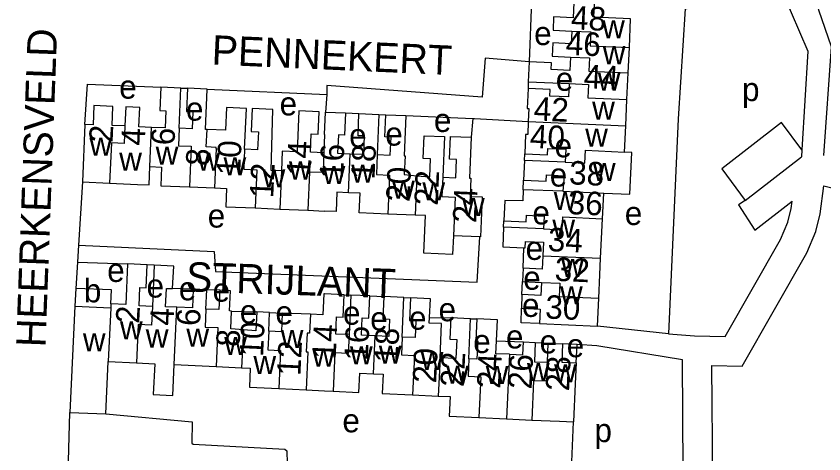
# Model space of a CAD drawing. Extents: x 163026 to 166241, y 382475 to 384501.
# Drawn here: x 164447.5 to 164584.9, y 383667.5 to 383742 of the extents above; entities that cross this region are included whole.
import ezdxf

# ---------------------------------------------------------------- set-up
doc = ezdxf.new("R2010")
doc.units = 0
for name, color, linetype in [('BLT_Basislijn', 7, 'Continuous'), ('BLT_Bebouwing', 7, 'Continuous'), ('BLT_Centroide', 7, 'Continuous'), ('BLT_Huisnummer', 7, 'Continuous'), ('BLT_Huisnummer_ tussenligend', 7, 'Continuous'), ('BLT_Onderverdeling_panden', 7, 'Continuous'), ('BLT_Straatnaam', 7, 'Continuous')]:
    doc.layers.add(name, color=color, linetype=linetype)

msp = doc.modelspace()

# ---------------------------------------------------------------- linework, layer by layer
at = {"layer": 'BLT_Basislijn'}
for p, q in [((164535.21, 383744.65), (164534.79, 383734.18)), ((164475.55, 383729.74), (164476.67, 383729.69)), ((164534.63, 383730.81), (164534.61, 383729.68)), ((164480.03, 383729.52), (164500.38, 383728.66)), ((164500.38, 383728.66), (164500.16, 383725.65)), ((164503.56, 383725.5), (164505.84, 383725.38)), ((164509.24, 383725.25), (164510.39, 383725.18)), ((164513.81, 383725.04), (164525.23, 383724.55)), ((164525.23, 383724.55), (164524.94, 383721.35)), ((164581.21, 383719.23), (164581.14, 383718.04)), ((164534.01, 383717.42), (164534.04, 383718.52)), ((164571.54, 383710.61), (164581.14, 383718.04)), ((164458.78, 383713.75), (164458.11, 383702.99)), ((164533.79, 383712.41), (164533.86, 383714.05)), ((164540.54, 383712.17), (164533.79, 383712.41)), ((164530.45, 383706.08), (164530.5, 383707.16)), ((164458.11, 383702.99), (164457.93, 383700.11)), ((164533.77, 383699.08), (164533.87, 383702.57)), ((164457.93, 383700.11), (164457.65, 383695.65)), ((164457.93, 383700.11), (164466.47, 383699.83)), ((164471.02, 383699.6), (164469.81, 383699.67)), ((164533.57, 383694.58), (164533.67, 383696.8)), ((164477.65, 383695.49), (164474.14, 383695.6)), ((164482.15, 383695.32), (164479.96, 383695.38)), ((164503.3, 383694.56), (164504.46, 383694.51)), ((164507.67, 383694.36), (164510.06, 383694.24)), ((164513.49, 383694.1), (164514.59, 383694.05)), ((164484.17, 383691.79), (164488.46, 383691.66)), ((164490.62, 383691.56), (164492.8, 383691.45)), ((164517.85, 383690.69), (164521.45, 383690.64)), ((164524.82, 383690.49), (164525.91, 383690.44)), ((164558.49, 383687.93), (164546.42, 383689.23)), ((164529.25, 383686.71), (164533.84, 383686.53)), ((164535.84, 383686.42), (164538.04, 383686.33)), ((164542.99, 383686.07), (164540.49, 383686.22)), ((164542.79, 383682.98), (164542.99, 383686.07)), ((164561.01, 383664.59), (164560.89, 383683.49))]:
    msp.add_line(p, q, dxfattribs=at)
for points in [[(164584.94, 383718.24), (164586.21, 383736.75), (164584.06, 383743.01), (164583.2, 383746.85), (164590.25, 383746.86)], [(164561.35, 383743.23), (164577.98, 383745.92), (164582.22, 383736), (164581.21, 383719.23)], [(164561.35, 383743.23), (164560.12, 383724.5), (164558.49, 383687.93)], [(164534.79, 383734.18), (164527.29, 383734.8), (164526.79, 383728.2), (164500.37, 383730.18), (164500.38, 383728.66)], [(164459.2, 383723.55), (164459.66, 383730.38), (164472.11, 383729.88)], [(164525.23, 383724.55), (164525.51, 383724.54), (164534.65, 383724.04)], [(164581.21, 383719.23), (164577.74, 383723.87), (164567.6, 383716), (164571.54, 383710.61)], [(164584.92, 383713.1), (164603, 383708.67), (164611.04, 383683.41), (164605.18, 383660.67), (164604, 383657.93), (164602.56, 383656.05), (164599.82, 383654.68), (164592.55, 383651.8), (164575.01, 383655.48), (164566.02, 383663.02), (164565.9, 383682.51)], [(164565.9, 383682.51), (164571.04, 383682.38), (164582.02, 383701.72), (164583.58, 383705.35), (164584.29, 383708.32), (164584.92, 383713.1)], [(164558.49, 383687.93), (164562.94, 383687.59), (164568.17, 383687.46), (164577.53, 383703.95), (164578.82, 383706.93), (164579.36, 383709.23), (164579.53, 383710.47)], [(164571.54, 383710.61), (164570.39, 383709.87), (164573.19, 383705.57), (164579.53, 383710.47)], [(164458.11, 383702.99), (164481.18, 383701.92), (164481.43, 383698.51), (164525.97, 383696.68), (164526.38, 383704.4)], [(164536.57, 383689.68), (164533.41, 383689.78), (164533.47, 383692.26)], [(164560.89, 383683.49), (164546.32, 383685.88), (164542.99, 383686.07)], [(164462.39, 383659.57), (164456.22, 383660.08), (164456.33, 383662.17), (164456.66, 383674.55)], [(164462.75, 383674.27), (164477.46, 383672.96), (164477.4, 383669.3), (164477.64, 383669.11), (164493.2, 383668.31), (164493.58, 383668.02), (164493.65, 383665.84), (164494.01, 383665.39), (164538.67, 383663.4)], [(164538.67, 383663.4), (164541.96, 383663.43), (164542.34, 383672.92)]]:
    msp.add_lwpolyline(points, dxfattribs=at)
at = {"layer": 'BLT_Bebouwing'}
for p, q in [((164551.64, 383732.3), (164551.84, 383736.62)), ((164534.79, 383734.18), (164534.63, 383730.81)), ((164551.43, 383727.77), (164551.64, 383732.3)), ((164475.55, 383729.74), (164472.11, 383729.88)), ((164480.03, 383729.52), (164476.67, 383729.69)), ((164551.22, 383723.28), (164551.43, 383727.77)), ((164500, 383721.83), (164500.16, 383725.65)), ((164500.16, 383725.65), (164503.56, 383725.5)), ((164505.84, 383725.38), (164509.24, 383725.25)), ((164510.39, 383725.18), (164513.81, 383725.04)), ((164459.2, 383723.55), (164458.78, 383713.75)), ((164551.02, 383718.85), (164551.22, 383723.28)), ((164534.01, 383717.42), (164533.86, 383714.05)), ((164458.78, 383713.75), (164463.42, 383713.55)), ((164477, 383712.91), (164481.27, 383712.73)), ((164533.79, 383712.41), (164533.71, 383710.53)), ((164547.3, 383707.49), (164547.5, 383711.85)), ((164488.17, 383709.33), (164492.37, 383709.14)), ((164492.37, 383709.14), (164497.15, 383708.94)), ((164497.15, 383708.94), (164500, 383708.81)), ((164515.38, 383708.11), (164510.74, 383708.3)), ((164546.95, 383700.76), (164547.3, 383707.49)), ((164526.38, 383704.4), (164521.9, 383704.59)), ((164469.81, 383699.67), (164466.47, 383699.83)), ((164533.77, 383699.08), (164533.67, 383696.8)), ((164457.65, 383695.65), (164457.51, 383692.64)), ((164479.96, 383695.38), (164477.65, 383695.49)), ((164503.3, 383694.56), (164500, 383694.71)), ((164507.67, 383694.36), (164504.46, 383694.51)), ((164513.49, 383694.1), (164510.06, 383694.24)), ((164533.57, 383694.58), (164533.47, 383692.26)), ((164546.42, 383689.23), (164546.64, 383693.97)), ((164457.51, 383692.64), (164456.66, 383674.55)), ((164490.62, 383691.56), (164488.46, 383691.66)), ((164497.59, 383691.23), (164492.8, 383691.45)), ((164517.81, 383689.71), (164517.85, 383690.69)), ((164521.45, 383690.64), (164521.29, 383687.01)), ((164524.82, 383690.49), (164521.45, 383690.64)), ((164536.57, 383689.68), (164546.42, 383689.23)), ((164533.84, 383686.53), (164535.84, 383686.42)), ((164538.04, 383686.33), (164540.49, 383686.22)), ((164462.75, 383674.27), (164463.17, 383683.18)), ((164463.17, 383683.18), (164467.97, 383682.95)), ((164481.54, 383682.35), (164485.87, 383682.14)), ((164492.2, 383678.58), (164496.83, 383678.36)), ((164496.83, 383678.36), (164500, 383678.21)), ((164500, 383678.21), (164501.47, 383678.15)), ((164514.97, 383677.51), (164519.33, 383677.31)), ((164456.66, 383674.55), (164462.75, 383674.27)), ((164526.26, 383673.65), (164530.95, 383673.44)), ((164530.95, 383673.44), (164535.27, 383673.24))]:
    msp.add_line(p, q, dxfattribs=at)
for points in [[(164542.38, 383744.28), (164542.26, 383741.71), (164538.96, 383741.86), (164538.86, 383739.59), (164542.07, 383739.44)], [(164551.84, 383736.62), (164552.06, 383741.49), (164545.82, 383741.78), (164545.93, 383744.12)], [(164542.07, 383739.44), (164541.97, 383737.27), (164538.82, 383737.42), (164538.72, 383735.16), (164541.85, 383735.01)], [(164541.85, 383735.01), (164541.74, 383732.75), (164538.56, 383732.9), (164538.61, 383734.01), (164534.79, 383734.18)], [(164472.11, 383729.88), (164471.94, 383725.89), (164472.97, 383725.85), (164472.85, 383722.95), (164470.57, 383723.05)], [(164475.26, 383722.9), (164475.55, 383729.74)], [(164476.67, 383729.69), (164476.51, 383725.72), (164477.56, 383725.67), (164477.44, 383722.8), (164475.26, 383722.9)], [(164534.61, 383729.68), (164534.45, 383726.27), (164534.75, 383726.26), (164534.65, 383724.04)], [(164541.61, 383730.49), (164541.51, 383728.23), (164538.34, 383728.37), (164538.39, 383729.5), (164534.61, 383729.68)], [(164534.63, 383730.81), (164541.61, 383730.49)], [(164479.99, 383722.69), (164479.75, 383722.7), (164480.03, 383729.52)], [(164466.02, 383723.28), (164463.84, 383723.37), (164463.98, 383726.6), (164460.75, 383726.74), (164460.61, 383723.49), (164459.2, 383723.55)], [(164470.57, 383723.05), (164468.39, 383723.14), (164468.53, 383726.44), (164466.15, 383726.54), (164466.02, 383723.28)], [(164486.39, 383719.31), (164486.68, 383726.27), (164483.31, 383726.41), (164483.14, 383722.56), (164479.99, 383722.69)], [(164492.65, 383715.65), (164490.89, 383715.73), (164491.2, 383726.08), (164487.65, 383726.23), (164487.49, 383722.35), (164488.72, 383722.3), (164488.59, 383719.21), (164486.39, 383719.31)], [(164499.87, 383718.72), (164497.58, 383718.82), (164497.71, 383721.93), (164498.89, 383721.88), (164499.05, 383725.69), (164495.62, 383725.84), (164495.33, 383718.88), (164492.79, 383718.98), (164492.65, 383715.65)], [(164503.56, 383725.5), (164503.4, 383721.71), (164502.33, 383721.76), (164502.2, 383718.66), (164504.33, 383718.57)], [(164504.33, 383718.57), (164506.65, 383718.47), (164506.78, 383721.59), (164505.68, 383721.63), (164505.84, 383725.38)], [(164509.24, 383725.25), (164508.96, 383718.42)], [(164508.96, 383718.42), (164511.17, 383718.33), (164511.3, 383721.37), (164510.24, 383721.42), (164510.39, 383725.18)], [(164513.81, 383725.04), (164513.53, 383718.21), (164513.68, 383718.2), (164513.55, 383715.01), (164515.66, 383714.82)], [(164534.65, 383724.04), (164534.55, 383721.83), (164534.19, 383721.84), (164534.04, 383718.52)], [(164500, 383721.83), (164499.87, 383718.72)], [(164515.66, 383714.82), (164517.87, 383714.64), (164518, 383717.71), (164516.78, 383717.76), (164516.94, 383721.61), (164520.37, 383721.47), (164520.08, 383714.58)], [(164520.08, 383714.58), (164522.32, 383714.48), (164522.45, 383717.59), (164521.26, 383717.64), (164521.43, 383721.49), (164524.94, 383721.35)], [(164524.94, 383721.35), (164524.65, 383714.42), (164524.9, 383714.41), (164524.77, 383711.29), (164526.82, 383711.2), (164526.54, 383704.39), (164526.38, 383704.4)], [(164534.04, 383718.52), (164537.9, 383718.35), (164537.96, 383719.47), (164541.03, 383719.33), (164540.93, 383717.1)], [(164547.5, 383711.85), (164551.94, 383711.67), (164552.27, 383718.79), (164551.02, 383718.85)], [(164540.93, 383717.1), (164534.01, 383717.42)], [(164463.42, 383713.55), (164468.16, 383713.34), (164470.14, 383713.26), (164470.28, 383716.37)], [(164470.28, 383716.37), (164472.27, 383716.29), (164472.13, 383713.12), (164477, 383712.91)], [(164533.86, 383714.05), (164537.69, 383713.87), (164537.74, 383714.95), (164540.73, 383714.81), (164540.54, 383712.17)], [(164481.27, 383712.73), (164483.33, 383712.64), (164483.2, 383709.54), (164488.17, 383709.33)], [(164504.05, 383711.92), (164502.08, 383712.01), (164501.94, 383708.73), (164500, 383708.81)], [(164510.74, 383708.3), (164505.88, 383708.51), (164506.02, 383711.84), (164504.05, 383711.92)], [(164533.71, 383710.53), (164530.66, 383710.62), (164530.5, 383707.16)], [(164521.9, 383704.59), (164521.77, 383701.43), (164516.9, 383701.63), (164517.17, 383708.04), (164515.38, 383708.11)], [(164530.5, 383707.16), (164534.27, 383706.98), (164534.32, 383708.09), (164537.36, 383707.95), (164537.26, 383705.76)], [(164530.45, 383706.08), (164530.29, 383702.74), (164533.87, 383702.57)], [(164537.26, 383705.76), (164530.45, 383706.08)], [(164533.87, 383702.57), (164534.13, 383702.56), (164534.18, 383703.63), (164537.21, 383703.49), (164537.1, 383701.21)], [(164537.1, 383701.21), (164537, 383698.93), (164533.77, 383699.08)], [(164546.64, 383693.97), (164546.82, 383697.93), (164546.95, 383700.76)], [(164466.47, 383699.83), (164466.15, 383692.88), (164463.63, 383693)], [(164470.69, 383692.57), (164468.42, 383692.67), (164468.56, 383695.8), (164469.63, 383695.75), (164469.81, 383699.67)], [(164471.02, 383699.6), (164470.69, 383692.57)], [(164474.14, 383695.6), (164474.32, 383699.45), (164471.02, 383699.6)], [(164536.88, 383696.66), (164536.78, 383694.44), (164533.57, 383694.58)], [(164533.67, 383696.8), (164536.88, 383696.66)], [(164463.63, 383693), (164463.74, 383695.37), (164457.65, 383695.65)], [(164474.86, 383692.43), (164472.94, 383692.53), (164473.09, 383695.65), (164474.14, 383695.6)], [(164477.65, 383695.49), (164477.5, 383692.31), (164474.86, 383692.43)], [(164479.81, 383692.13), (164479.96, 383695.38)], [(164482.15, 383695.32), (164482, 383692.03), (164479.81, 383692.13)], [(164484.17, 383691.79), (164483.84, 383691.8), (164484, 383695.23), (164482.15, 383695.32)], [(164500, 383694.71), (164499.86, 383694.71), (164499.69, 383691.17), (164497.59, 383691.23)], [(164504.16, 383687.77), (164501.89, 383687.87), (164502.03, 383690.81), (164503.13, 383690.76), (164503.3, 383694.56)], [(164504.46, 383694.51), (164504.16, 383687.77)], [(164508.6, 383687.55), (164506.27, 383687.66), (164506.4, 383690.62), (164507.5, 383690.57), (164507.67, 383694.36)], [(164510.06, 383694.24), (164509.91, 383690.45), (164511.06, 383690.4), (164510.93, 383687.45), (164508.6, 383687.55)], [(164513.21, 383687.36), (164513.49, 383694.1)], [(164514.59, 383694.05), (164514.42, 383690.19), (164515.54, 383690.14), (164515.41, 383687.26), (164513.21, 383687.36)], [(164517.85, 383690.69), (164517.99, 383693.89), (164514.59, 383694.05)], [(164486.17, 383688.58), (164484.03, 383688.74), (164484.17, 383691.79)], [(164488.46, 383691.66), (164488.3, 383688.42), (164486.17, 383688.58)], [(164490.48, 383688.36), (164490.62, 383691.56)], [(164492.8, 383691.45), (164492.65, 383688.24), (164490.48, 383688.36)], [(164533.47, 383692.26), (164536.68, 383692.11), (164536.57, 383689.68)], [(164524.52, 383683.64), (164524.82, 383690.49)], [(164525.91, 383690.44), (164525.75, 383686.75), (164526.04, 383686.73), (164525.9, 383683.58), (164524.52, 383683.64)], [(164529.25, 383686.71), (164529.41, 383690.29), (164525.91, 383690.44)], [(164519.63, 383683.82), (164519.89, 383689.67), (164517.81, 383689.71)], [(164521.29, 383687.01), (164522.48, 383686.95), (164522.33, 383683.7), (164519.63, 383683.82)], [(164531.45, 383684.43), (164529.15, 383684.53), (164529.25, 383686.71)], [(164531.45, 383684.43), (164533.74, 383684.32), (164533.84, 383686.53)], [(164535.84, 383686.42), (164535.7, 383683.12), (164537.89, 383683.08)], [(164537.89, 383683.08), (164538.04, 383686.33)], [(164540.49, 383686.22), (164540.35, 383683.09), (164542.79, 383682.98)], [(164467.97, 383682.95), (164471.1, 383682.8), (164470.85, 383677.6), (164474.15, 383677.44), (164474.4, 383682.68)], [(164542.79, 383682.98), (164542.63, 383679.41), (164542.34, 383672.92)], [(164474.4, 383682.68), (164481.54, 383682.35)], [(164485.87, 383682.14), (164487.34, 383682.07), (164487.19, 383678.81), (164492.2, 383678.58)], [(164501.47, 383678.15), (164505.84, 383677.94), (164505.99, 383681.2), (164508.31, 383681.09)], [(164508.31, 383681.09), (164509.94, 383681.02), (164509.8, 383677.74), (164514.97, 383677.51)], [(164519.33, 383677.31), (164521.33, 383677.22), (164521.18, 383673.88), (164526.26, 383673.65)], [(164535.27, 383673.24), (164539.96, 383673.03), (164542.34, 383672.92)]]:
    msp.add_lwpolyline(points, dxfattribs=at)
at = {"layer": 'BLT_Onderverdeling_panden'}
for p, q in [((164470.28, 383716.37), (164470.57, 383723.05)), ((164534.65, 383724.04), (164551.22, 383723.28)), ((164481.56, 383719.45), (164481.27, 383712.73)), ((164504.05, 383711.92), (164504.33, 383718.57)), ((164492.65, 383715.65), (164492.37, 383709.14)), ((164515.66, 383714.82), (164515.38, 383708.11)), ((164540.54, 383712.17), (164547.5, 383711.85)), ((164537.1, 383701.21), (164546.95, 383700.76)), ((164457.51, 383692.64), (164463.6, 383692.35)), ((164463.63, 383693), (164463.6, 383692.35)), ((164463.6, 383692.35), (164463.17, 383683.18)), ((164474.4, 383682.68), (164474.86, 383692.43)), ((164486.17, 383688.58), (164485.87, 383682.14)), ((164508.31, 383681.09), (164508.6, 383687.55)), ((164531.45, 383684.43), (164530.95, 383673.44)), ((164519.63, 383683.82), (164519.33, 383677.31))]:
    msp.add_line(p, q, dxfattribs=at)
for points in [[(164542.07, 383739.44), (164545.28, 383739.29), (164545.17, 383736.92), (164551.84, 383736.62)], [(164541.85, 383735.01), (164545.08, 383734.86), (164544.97, 383732.6), (164551.64, 383732.3)], [(164541.61, 383730.49), (164544.87, 383730.34), (164544.76, 383728.08), (164551.43, 383727.77)], [(164466.02, 383723.28), (164465.89, 383720.32), (164463.71, 383720.41), (164463.42, 383713.55)], [(164475.26, 383722.9), (164475.13, 383719.91), (164477.31, 383719.82), (164477, 383712.91)], [(164481.56, 383719.45), (164481.57, 383719.63), (164479.86, 383719.71), (164479.99, 383722.69)], [(164486.39, 383719.31), (164486.24, 383715.92), (164488.45, 383715.83), (164488.17, 383709.33)], [(164499.87, 383718.72), (164499.73, 383715.35), (164497.44, 383715.44), (164497.15, 383708.94)], [(164540.93, 383717.1), (164544.25, 383716.94), (164544.36, 383719.17), (164551.02, 383718.85)], [(164508.96, 383718.42), (164508.83, 383715), (164511.02, 383714.91), (164510.74, 383708.3)], [(164520.08, 383714.58), (164519.93, 383711.26), (164522.18, 383711.16), (164521.9, 383704.59)], [(164537.26, 383705.76), (164540.41, 383705.61), (164540.51, 383707.8), (164547.3, 383707.49)], [(164536.88, 383696.66), (164540, 383696.51), (164539.9, 383694.29), (164546.64, 383693.97)], [(164470.69, 383692.57), (164470.54, 383689.38), (164468.27, 383689.49), (164467.97, 383682.95)], [(164479.81, 383692.13), (164479.66, 383689.06), (164481.85, 383688.96), (164481.54, 383682.35)], [(164497.59, 383691.23), (164497.45, 383688.03), (164497.02, 383688.05)], [(164490.48, 383688.36), (164490.33, 383685.17), (164492.5, 383685.07), (164492.2, 383678.58)], [(164497.02, 383688.05), (164496.87, 383684.87), (164497.14, 383684.86), (164496.83, 383678.36)], [(164504.16, 383687.77), (164504.01, 383684.55), (164501.75, 383684.65), (164501.47, 383678.15)], [(164513.21, 383687.36), (164513.07, 383684.32), (164515.27, 383684.22), (164514.97, 383677.51)], [(164524.52, 383683.64), (164524.39, 383680.68), (164526.57, 383680.58), (164526.26, 383673.65)], [(164537.89, 383683.08), (164537.74, 383679.84), (164535.56, 383679.94), (164535.27, 383673.24)]]:
    msp.add_lwpolyline(points, dxfattribs=at)

# ---------------------------------------------------------------- texts
at = {"layer": 'BLT_Centroide'}
for s, p in [('w', (164547.21, 383738.2)), ('e', (164535.64, 383737.05)), ('w', (164547.31, 383733.8)), ('e', (164539.32, 383729.27)), ('w', (164546.46, 383729.3)), ('e', (164465.05, 383727.93)), ('p', (164571.01, 383727.52)), ('e', (164476.41, 383724.19)), ('e', (164492.34, 383725.08)), ('w', (164545.51, 383724.34)), ('e', (164518.59, 383722.26)), ('e', (164504.17, 383719.67)), ('e', (164510.31, 383719.94)), ('w', (164544.33, 383719.78)), ('w', (164459.98, 383718.21)), ('e', (164539.11, 383717.95)), ('w', (164465.05, 383715.66)), ('w', (164471.25, 383716.7)), ('w', (164478.34, 383715.66)), ('w', (164482.8, 383714.89)), ('w', (164493.94, 383714.17)), ('w', (164489.44, 383712.82)), ('w', (164499.65, 383713.41)), ('w', (164504.53, 383713.65)), ('e', (164538.3, 383712.97)), ('w', (164545.64, 383713.91)), ('w', (164511.47, 383710.9)), ('w', (164516.63, 383710.63)), ('w', (164538.98, 383709)), ('w', (164523.38, 383707.98)), ('e', (164480.11, 383705.99)), ('e', (164535.35, 383706.53)), ('e', (164551.06, 383706.43)), ('w', (164538.74, 383704.28)), ('e', (164534.19, 383700.49)), ('e', (164463, 383696.74)), ('w', (164540.25, 383697.59)), ('e', (164533.78, 383695.42)), ('b', (164459.03, 383693.27)), ('e', (164469.7, 383694.08)), ('e', (164475.19, 383693.61)), ('e', (164480.93, 383693.38)), ('w', (164540.05, 383692.94)), ('e', (164533.58, 383690.79)), ('e', (164485.56, 383689.71)), ('e', (164491.63, 383689.52)), ('e', (164503.13, 383689.46)), ('e', (164519.38, 383690.05)), ('e', (164507.75, 383688.51)), ('e', (164514.36, 383688.62)), ('w', (164465.18, 383686.95)), ('w', (164469.57, 383685.58)), ('w', (164476.48, 383685.71)), ('w', (164492.53, 383685.51)), ('e', (164530.85, 383685.42)), ('w', (164458.87, 383684.95)), ('w', (164482.91, 383684.32)), ('e', (164525.27, 383684.64)), ('e', (164536.57, 383684.58)), ('e', (164541.19, 383683.93)), ('w', (164504.31, 383682.7)), ('w', (164509.23, 383682.82)), ('w', (164497.88, 383682.3)), ('w', (164516.35, 383681.75)), ('w', (164487.88, 383681.07)), ('w', (164534.42, 383679.89)), ('w', (164520.68, 383679.44)), ('w', (164527.41, 383679.38)), ('w', (164539.03, 383679.67)), ('e', (164503.02, 383671.15)), ('p', (164545.9, 383669.49))]:
    msp.add_text(s, height=4, dxfattribs=at).set_placement(p)
at = {"layer": 'BLT_Huisnummer'}
for s, rotation, p in [('48', 357.3655, (164541.85, 383739.74)), ('42', 357.3655, (164535.51, 383724.25)), ('2', 87.5277, (164463.92, 383720.38)), ('6', 87.5277, (164474.45, 383719.94)), ('10', 87.5277, (164485.62, 383714.81)), ('14', 87.5277, (164497.53, 383714.7)), ('18', 87.5277, (164508.48, 383714.12)), ('38', 357.3655, (164541.53, 383713.37)), ('24', 87.5277, (164525.78, 383706.73)), ('34', 357.3655, (164537.9, 383702)), ('30', 357.3655, (164537.47, 383690.53)), ('2', 87.3217, (164468.45, 383689.61)), ('6', 87.3217, (164478.78, 383689.18)), ('10', 87.3217, (164489.52, 383683.96)), ('14', 87.3217, (164501.87, 383683.51)), ('18', 87.3217, (164512.43, 383682.93)), ('22', 87.3217, (164523.66, 383678.8)), ('28', 87.3217, (164541.58, 383678.1))]:
    msp.add_text(s, height=4, rotation=rotation, dxfattribs=at).set_placement(p)
at = {"layer": 'BLT_Huisnummer_ tussenligend'}
for s, rotation, p in [('46', 357.3655, (164540.95, 383735.41)), ('44', 357.3655, (164544.01, 383729.75)), ('4', 87.5277, (164469.38, 383719.88)), ('40', 357.3655, (164534.85, 383719.56)), ('16', 87.5277, (164503.11, 383714.22)), ('8', 87.5277, (164480.37, 383716.43)), ('12', 87.5277, (164491.25, 383710.95)), ('20', 87.5277, (164514.44, 383710.31)), ('22', 87.5277, (164519.24, 383709.69)), ('36', 357.3655, (164541.28, 383708.31)), ('32', 357.3655, (164539.08, 383696.95)), ('4', 87.3217, (164474.27, 383689.24)), ('8', 87.3217, (164485.52, 383685.63)), ('16', 87.3217, (164507.33, 383683.27)), ('12', 87.3217, (164495.87, 383680.7)), ('20', 87.3217, (164518.96, 383679.46)), ('24', 87.3217, (164529.88, 383678.55)), ('26', 87.3217, (164535.21, 383678.43))]:
    msp.add_text(s, height=4, rotation=rotation, dxfattribs=at).set_placement(p)
at = {"layer": 'BLT_Straatnaam'}
for s, rotation, p in [('HEERKENSVELD', 87.8726, (164452.49, 383685.57)), ('PENNEKERT', 357.4719, (164480.71, 383733.75)), ('STRIJLANT', 358.0587, (164476.36, 383695.15))]:
    msp.add_text(s, height=5, rotation=rotation, dxfattribs=at).set_placement(p)

doc.saveas('drawing.dxf')
